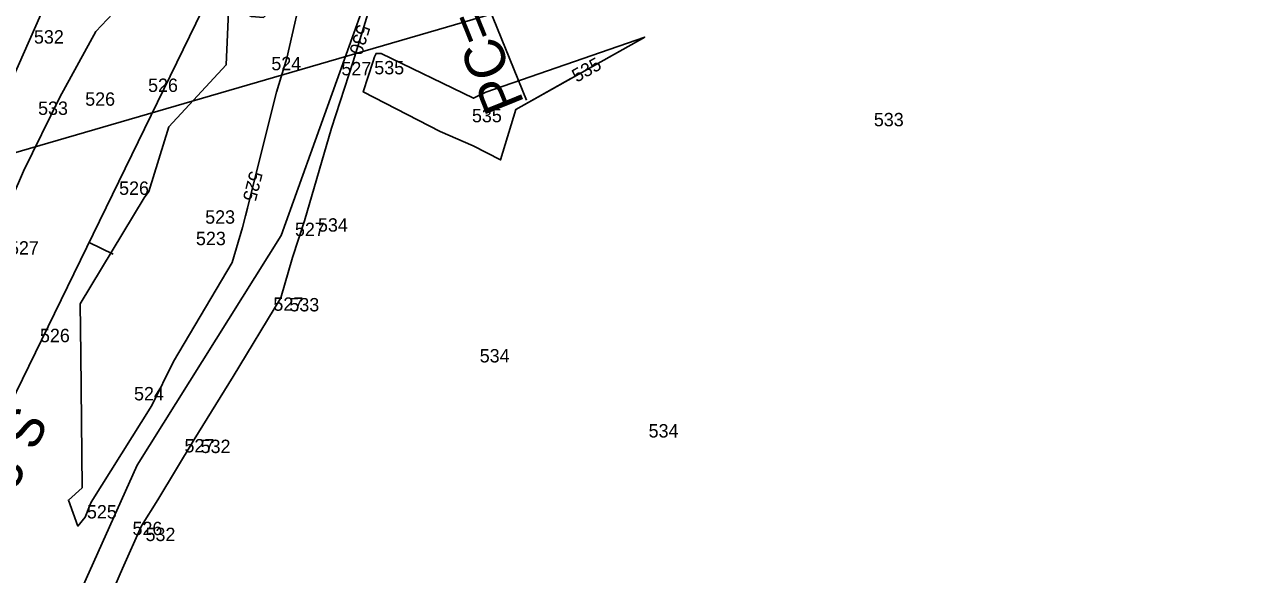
# Model space of a CAD drawing. Extents: x 1787461 to 1970323, y 938412 to 1118748.
# Drawn here: x 1967816.7 to 1967999.8, y 1117714.7 to 1117796.9 of the extents above; entities that cross this region are included whole.
import ezdxf

# ---------------------------------------------------------------- set-up
doc = ezdxf.new("R2010")
doc.units = 0
for name, color, linetype in [('Default', 7, 'Continuous'), ('HHA ADDITIONAL XSs', 7, 'Continuous'), ('Level 1', 7, 'Continuous'), ('RD_EX_DV_Prop', 7, 'Continuous'), ('RD_EX_H2O', 7, 'Continuous'), ('RD_HC_CL', 7, 'Continuous'), ('RD_HC_Data', 7, 'Continuous'), ('RD_HC_Data_Tic', 7, 'Continuous')]:
    doc.layers.add(name, color=color, linetype=linetype)

msp = doc.modelspace()

# ---------------------------------------------------------------- linework, layer by layer
at = {"layer": 'Default'}
for points in [[(1967801.88, 1117847.61), (1967810.59, 1117836.47), (1967817.97, 1117828.1), (1967825.91, 1117816.75), (1967828.59, 1117812.93), (1967832.36, 1117808.61), (1967834.19, 1117807.04), (1967834.93, 1117806.3), (1967834.88, 1117806.26), (1967831.61, 1117800.38), (1967827.33, 1117795.88), (1967821.98, 1117786.05), (1967816.55, 1117775), (1967811.53, 1117763.56), (1967808.3, 1117757.03), (1967806.64, 1117753.26), (1967802.17, 1117742.25), (1967796.95, 1117730.25), (1967792.24, 1117718.65), (1967787.4, 1117707.51)], [(1967801.88, 1117847.61), (1967810.59, 1117836.47), (1967817.97, 1117828.1), (1967825.91, 1117816.75), (1967828.59, 1117812.93), (1967832.36, 1117808.61), (1967834.19, 1117807.04), (1967834.93, 1117806.3), (1967834.88, 1117806.26), (1967831.61, 1117800.38), (1967827.33, 1117795.88), (1967821.98, 1117786.05), (1967816.55, 1117775), (1967811.53, 1117763.56), (1967808.3, 1117757.03), (1967806.64, 1117753.26), (1967802.17, 1117742.25), (1967796.95, 1117730.25), (1967792.24, 1117718.65), (1967787.4, 1117707.51)], [(1967801.88, 1117847.61), (1967810.59, 1117836.47), (1967817.97, 1117828.1), (1967825.91, 1117816.75), (1967828.59, 1117812.93), (1967832.36, 1117808.61), (1967834.19, 1117807.04), (1967834.93, 1117806.3), (1967834.88, 1117806.26), (1967831.61, 1117800.38), (1967827.33, 1117795.88), (1967821.98, 1117786.05), (1967816.55, 1117775), (1967811.53, 1117763.56), (1967808.3, 1117757.03), (1967806.64, 1117753.26), (1967802.17, 1117742.25), (1967796.95, 1117730.25), (1967792.24, 1117718.65), (1967787.4, 1117707.51)], [(1967801.88, 1117847.61), (1967810.59, 1117836.47), (1967817.97, 1117828.1), (1967825.91, 1117816.75), (1967828.59, 1117812.93), (1967832.36, 1117808.61), (1967834.19, 1117807.04), (1967834.93, 1117806.3), (1967834.88, 1117806.26), (1967831.61, 1117800.38), (1967827.33, 1117795.88), (1967821.98, 1117786.05), (1967816.55, 1117775), (1967811.53, 1117763.56), (1967808.3, 1117757.03), (1967806.64, 1117753.26), (1967802.17, 1117742.25), (1967796.95, 1117730.25), (1967792.24, 1117718.65), (1967787.4, 1117707.51)], [(1967801.88, 1117847.61), (1967810.59, 1117836.47), (1967817.97, 1117828.1), (1967825.91, 1117816.75), (1967828.59, 1117812.93), (1967832.36, 1117808.61), (1967834.19, 1117807.04), (1967834.93, 1117806.3), (1967834.88, 1117806.26), (1967831.61, 1117800.38), (1967827.33, 1117795.88), (1967821.98, 1117786.05), (1967816.55, 1117775), (1967811.53, 1117763.56), (1967808.3, 1117757.03), (1967806.64, 1117753.26), (1967802.17, 1117742.25), (1967796.95, 1117730.25), (1967792.24, 1117718.65), (1967787.4, 1117707.51)], [(1967801.88, 1117847.61), (1967810.59, 1117836.47), (1967817.97, 1117828.1), (1967825.91, 1117816.75), (1967828.59, 1117812.93), (1967832.36, 1117808.61), (1967834.19, 1117807.04), (1967834.93, 1117806.3), (1967834.88, 1117806.26), (1967831.61, 1117800.38), (1967827.33, 1117795.88), (1967821.98, 1117786.05), (1967816.55, 1117775), (1967811.53, 1117763.56), (1967808.3, 1117757.03), (1967806.64, 1117753.26), (1967802.17, 1117742.25), (1967796.95, 1117730.25), (1967792.24, 1117718.65), (1967787.4, 1117707.51)], [(1967810.59, 1117836.47), (1967817.97, 1117828.1), (1967825.91, 1117816.75), (1967828.59, 1117812.93), (1967832.36, 1117808.61), (1967834.19, 1117807.04), (1967834.93, 1117806.3), (1967834.88, 1117806.26), (1967831.61, 1117800.38), (1967827.33, 1117795.88), (1967821.98, 1117786.05), (1967816.55, 1117775)], [(1967825.01, 1117755.18), (1967834.57, 1117771.02), (1967835.27, 1117771.98), (1967838.28, 1117781.65), (1967846.84, 1117790.9), (1967847.21, 1117799.97), (1967850.61, 1117798.14), (1967852.43, 1117798), (1967858.52, 1117803.53), (1967855.88, 1117791.92), (1967854.34, 1117786.82), (1967849.71, 1117768.33), (1967849.28, 1117766.59), (1967847.71, 1117761.38), (1967838.96, 1117746.55), (1967835.72, 1117740.01), (1967826.65, 1117725.53), (1967826.39, 1117724.96), (1967825.77, 1117723.3), (1967824.68, 1117721.97), (1967823.26, 1117725.85), (1967825.32, 1117727.69), (1967825.09, 1117747.68), (1967825.01, 1117755.18)], [(1967824.16, 1117699.1), (1967831.36, 1117715.62), (1967834.2, 1117721.99), (1967836.61, 1117725.9), (1967842.06, 1117734.92), (1967847.86, 1117744.33), (1967854.99, 1117756.1), (1967856.74, 1117762.12), (1967858.55, 1117767.59), (1967862.58, 1117781.44), (1967865.81, 1117791.38), (1967869.95, 1117804.92)], [(1967825.01, 1117755.18), (1967834.57, 1117771.02), (1967835.27, 1117771.98), (1967838.28, 1117781.65), (1967846.84, 1117790.9), (1967847.21, 1117799.97), (1967850.61, 1117798.14), (1967852.43, 1117798), (1967858.52, 1117803.53), (1967855.88, 1117791.92), (1967854.34, 1117786.82), (1967851.45, 1117775.29)], [(1967825.01, 1117755.18), (1967834.57, 1117771.02), (1967835.27, 1117771.98), (1967838.28, 1117781.65), (1967846.84, 1117790.9), (1967847.21, 1117799.97), (1967850.61, 1117798.14), (1967852.43, 1117798), (1967858.52, 1117803.53), (1967855.88, 1117791.92), (1967854.34, 1117786.82), (1967851.45, 1117775.29)], [(1967825.01, 1117755.18), (1967834.57, 1117771.02), (1967835.27, 1117771.98), (1967838.28, 1117781.65), (1967846.84, 1117790.9), (1967847.21, 1117799.97), (1967850.61, 1117798.14), (1967852.43, 1117798), (1967858.52, 1117803.53), (1967855.88, 1117791.92), (1967854.34, 1117786.82), (1967851.45, 1117775.29)], [(1967825.01, 1117755.18), (1967834.57, 1117771.02), (1967835.27, 1117771.98), (1967838.28, 1117781.65), (1967846.84, 1117790.9), (1967847.21, 1117799.97), (1967850.61, 1117798.14), (1967852.43, 1117798), (1967858.52, 1117803.53), (1967855.88, 1117791.92), (1967854.34, 1117786.82), (1967851.45, 1117775.29)], [(1967825.01, 1117755.18), (1967834.57, 1117771.02), (1967835.27, 1117771.98), (1967838.28, 1117781.65), (1967846.84, 1117790.9), (1967847.21, 1117799.97), (1967850.61, 1117798.14), (1967852.43, 1117798), (1967858.52, 1117803.53), (1967855.88, 1117791.92), (1967854.34, 1117786.82), (1967851.45, 1117775.29)], [(1967825.01, 1117755.18), (1967834.57, 1117771.02), (1967835.27, 1117771.98), (1967838.28, 1117781.65), (1967846.84, 1117790.9), (1967847.21, 1117799.97), (1967850.61, 1117798.14), (1967852.43, 1117798), (1967858.52, 1117803.53), (1967855.88, 1117791.92), (1967854.34, 1117786.82), (1967851.45, 1117775.29)], [(1967868.82, 1117791.47), (1967869.02, 1117792.12), (1967869.25, 1117792.62), (1967870.02, 1117792.58), (1967883.8, 1117785.91), (1967885.65, 1117786.84), (1967909.41, 1117795.06), (1967890.14, 1117784.25), (1967887.87, 1117776.68), (1967883.76, 1117778.78), (1967878.84, 1117780.96), (1967867.32, 1117786.85), (1967868.82, 1117791.47)], [(1967868.82, 1117791.47), (1967869.02, 1117792.12), (1967869.25, 1117792.62), (1967870.02, 1117792.58), (1967883.8, 1117785.91), (1967885.65, 1117786.84), (1967909.41, 1117795.06), (1967903.62, 1117791.81)], [(1967868.82, 1117791.47), (1967869.02, 1117792.12), (1967869.25, 1117792.62), (1967870.02, 1117792.58), (1967883.8, 1117785.91), (1967885.65, 1117786.84), (1967909.41, 1117795.06), (1967903.62, 1117791.81)], [(1967868.82, 1117791.47), (1967869.02, 1117792.12), (1967869.25, 1117792.62), (1967870.02, 1117792.58), (1967883.8, 1117785.91), (1967885.65, 1117786.84), (1967909.41, 1117795.06), (1967903.62, 1117791.81)], [(1967868.82, 1117791.47), (1967869.02, 1117792.12), (1967869.25, 1117792.62), (1967870.02, 1117792.58), (1967883.8, 1117785.91), (1967885.65, 1117786.84), (1967909.41, 1117795.06), (1967903.62, 1117791.81)], [(1967868.82, 1117791.47), (1967869.02, 1117792.12), (1967869.25, 1117792.62), (1967870.02, 1117792.58), (1967883.8, 1117785.91), (1967885.65, 1117786.84), (1967909.41, 1117795.06), (1967903.62, 1117791.81)], [(1967868.82, 1117791.47), (1967869.02, 1117792.12), (1967869.25, 1117792.62), (1967870.02, 1117792.58), (1967883.8, 1117785.91), (1967885.65, 1117786.84), (1967909.41, 1117795.06), (1967903.62, 1117791.81)], [(1967785.77, 1117609.46), (1967789.86, 1117617.86), (1967798.49, 1117629.43), (1967798.85, 1117630.5), (1967799.16, 1117631.38), (1967803.98, 1117645.6), (1967807.24, 1117654.97), (1967814.41, 1117676.3), (1967815.2, 1117678.59), (1967815.94, 1117680.25), (1967824.16, 1117699.1), (1967831.36, 1117715.62), (1967834.2, 1117721.99), (1967836.61, 1117725.9), (1967842.06, 1117734.92), (1967847.86, 1117744.33), (1967854.99, 1117756.1), (1967856.74, 1117762.12), (1967858.55, 1117767.59), (1967862.58, 1117781.44), (1967865.81, 1117791.38), (1967865.83, 1117791.44)], [(1967785.77, 1117609.46), (1967789.86, 1117617.86), (1967798.49, 1117629.43), (1967798.85, 1117630.5), (1967799.16, 1117631.38), (1967803.98, 1117645.6), (1967807.24, 1117654.97), (1967814.41, 1117676.3), (1967815.2, 1117678.59), (1967815.94, 1117680.25), (1967824.16, 1117699.1), (1967831.36, 1117715.62), (1967834.2, 1117721.99), (1967836.61, 1117725.9), (1967842.06, 1117734.92), (1967847.86, 1117744.33), (1967854.99, 1117756.1), (1967856.74, 1117762.12), (1967858.55, 1117767.59), (1967862.58, 1117781.44), (1967865.81, 1117791.38), (1967865.83, 1117791.44)], [(1967785.77, 1117609.46), (1967789.86, 1117617.86), (1967798.49, 1117629.43), (1967798.85, 1117630.5), (1967799.16, 1117631.38), (1967803.98, 1117645.6), (1967807.24, 1117654.97), (1967814.41, 1117676.3), (1967815.2, 1117678.59), (1967815.94, 1117680.25), (1967824.16, 1117699.1), (1967831.36, 1117715.62), (1967834.2, 1117721.99), (1967836.61, 1117725.9), (1967842.06, 1117734.92), (1967847.86, 1117744.33), (1967854.99, 1117756.1), (1967856.74, 1117762.12), (1967858.55, 1117767.59), (1967862.58, 1117781.44), (1967865.81, 1117791.38), (1967865.83, 1117791.44)], [(1967785.77, 1117609.46), (1967789.86, 1117617.86), (1967798.49, 1117629.43), (1967798.85, 1117630.5), (1967799.16, 1117631.38), (1967803.98, 1117645.6), (1967807.24, 1117654.97), (1967814.41, 1117676.3), (1967815.2, 1117678.59), (1967815.94, 1117680.25), (1967824.16, 1117699.1), (1967831.36, 1117715.62), (1967834.2, 1117721.99), (1967836.61, 1117725.9), (1967842.06, 1117734.92), (1967847.86, 1117744.33), (1967854.99, 1117756.1), (1967856.74, 1117762.12), (1967858.55, 1117767.59), (1967862.58, 1117781.44), (1967865.81, 1117791.38), (1967865.83, 1117791.44)], [(1967785.77, 1117609.46), (1967789.86, 1117617.86), (1967798.49, 1117629.43), (1967798.85, 1117630.5), (1967799.16, 1117631.38), (1967803.98, 1117645.6), (1967807.24, 1117654.97), (1967814.41, 1117676.3), (1967815.2, 1117678.59), (1967815.94, 1117680.25), (1967824.16, 1117699.1), (1967831.36, 1117715.62), (1967834.2, 1117721.99), (1967836.61, 1117725.9), (1967842.06, 1117734.92), (1967847.86, 1117744.33), (1967854.99, 1117756.1), (1967856.74, 1117762.12), (1967858.55, 1117767.59), (1967862.58, 1117781.44), (1967865.81, 1117791.38), (1967865.83, 1117791.44)], [(1967785.77, 1117609.46), (1967789.86, 1117617.86), (1967798.49, 1117629.43), (1967798.85, 1117630.5), (1967799.16, 1117631.38), (1967803.98, 1117645.6), (1967807.24, 1117654.97), (1967814.41, 1117676.3), (1967815.2, 1117678.59), (1967815.94, 1117680.25), (1967824.16, 1117699.1), (1967831.36, 1117715.62), (1967834.2, 1117721.99), (1967836.61, 1117725.9), (1967842.06, 1117734.92), (1967847.86, 1117744.33), (1967854.99, 1117756.1), (1967856.74, 1117762.12), (1967858.55, 1117767.59), (1967862.58, 1117781.44), (1967865.81, 1117791.38), (1967865.83, 1117791.44)], [(1967898.38, 1117788.88), (1967890.14, 1117784.25), (1967887.87, 1117776.68), (1967883.76, 1117778.78), (1967878.84, 1117780.96), (1967867.32, 1117786.85), (1967868.82, 1117791.47)], [(1967898.38, 1117788.88), (1967890.14, 1117784.25), (1967887.87, 1117776.68), (1967883.76, 1117778.78), (1967878.84, 1117780.96), (1967867.32, 1117786.85), (1967868.82, 1117791.47)], [(1967898.38, 1117788.88), (1967890.14, 1117784.25), (1967887.87, 1117776.68), (1967883.76, 1117778.78), (1967878.84, 1117780.96), (1967867.32, 1117786.85), (1967868.82, 1117791.47)], [(1967898.38, 1117788.88), (1967890.14, 1117784.25), (1967887.87, 1117776.68), (1967883.76, 1117778.78), (1967878.84, 1117780.96), (1967867.32, 1117786.85), (1967868.82, 1117791.47)], [(1967898.38, 1117788.88), (1967890.14, 1117784.25), (1967887.87, 1117776.68), (1967883.76, 1117778.78), (1967878.84, 1117780.96), (1967867.32, 1117786.85), (1967868.82, 1117791.47)], [(1967898.38, 1117788.88), (1967890.14, 1117784.25), (1967887.87, 1117776.68), (1967883.76, 1117778.78), (1967878.84, 1117780.96), (1967867.32, 1117786.85), (1967868.82, 1117791.47)], [(1967850, 1117769.47), (1967849.71, 1117768.33), (1967849.28, 1117766.59), (1967847.71, 1117761.38), (1967838.96, 1117746.55), (1967835.72, 1117740.01), (1967826.65, 1117725.53), (1967826.39, 1117724.96), (1967825.77, 1117723.3), (1967824.68, 1117721.97), (1967823.26, 1117725.85), (1967825.32, 1117727.69), (1967825.09, 1117747.68), (1967825.01, 1117755.18)], [(1967850, 1117769.47), (1967849.71, 1117768.33), (1967849.28, 1117766.59), (1967847.71, 1117761.38), (1967838.96, 1117746.55), (1967835.72, 1117740.01), (1967826.65, 1117725.53), (1967826.39, 1117724.96), (1967825.77, 1117723.3), (1967824.68, 1117721.97), (1967823.26, 1117725.85), (1967825.32, 1117727.69), (1967825.09, 1117747.68), (1967825.01, 1117755.18)], [(1967850, 1117769.47), (1967849.71, 1117768.33), (1967849.28, 1117766.59), (1967847.71, 1117761.38), (1967838.96, 1117746.55), (1967835.72, 1117740.01), (1967826.65, 1117725.53), (1967826.39, 1117724.96), (1967825.77, 1117723.3), (1967824.68, 1117721.97), (1967823.26, 1117725.85), (1967825.32, 1117727.69), (1967825.09, 1117747.68), (1967825.01, 1117755.18)], [(1967850, 1117769.47), (1967849.71, 1117768.33), (1967849.28, 1117766.59), (1967847.71, 1117761.38), (1967838.96, 1117746.55), (1967835.72, 1117740.01), (1967826.65, 1117725.53), (1967826.39, 1117724.96), (1967825.77, 1117723.3), (1967824.68, 1117721.97), (1967823.26, 1117725.85), (1967825.32, 1117727.69), (1967825.09, 1117747.68), (1967825.01, 1117755.18)], [(1967850, 1117769.47), (1967849.71, 1117768.33), (1967849.28, 1117766.59), (1967847.71, 1117761.38), (1967838.96, 1117746.55), (1967835.72, 1117740.01), (1967826.65, 1117725.53), (1967826.39, 1117724.96), (1967825.77, 1117723.3), (1967824.68, 1117721.97), (1967823.26, 1117725.85), (1967825.32, 1117727.69), (1967825.09, 1117747.68), (1967825.01, 1117755.18)], [(1967850, 1117769.47), (1967849.71, 1117768.33), (1967849.28, 1117766.59), (1967847.71, 1117761.38), (1967838.96, 1117746.55), (1967835.72, 1117740.01), (1967826.65, 1117725.53), (1967826.39, 1117724.96), (1967825.77, 1117723.3), (1967824.68, 1117721.97), (1967823.26, 1117725.85), (1967825.32, 1117727.69), (1967825.09, 1117747.68), (1967825.01, 1117755.18)]]:
    msp.add_lwpolyline(points, dxfattribs=at)
at = {"layer": 'HHA ADDITIONAL XSs'}
msp.add_arc((1968231.34, 1116297.54), 1607.02, 87.72663, 111.99584, dxfattribs=at)
at = {"layer": 'Level 1'}
msp.add_lwpolyline([(1968654.57, 1117840.68), (1968058.24, 1117848.48), (1967686.38, 1117740.3), (1966964.76, 1117453.35)], dxfattribs=at)
at = {"layer": 'RD_EX_DV_Prop'}
msp.add_line((1967848.59, 1117809.96), (1967728.08, 1117563.01), dxfattribs=at)
at = {"layer": 'RD_EX_H2O'}
for points in [[(1967793.07, 1117884.81), (1967795.4, 1117862.79), (1967808.44, 1117844.76), (1967827.6, 1117817.64), (1967803.85, 1117763.92), (1967785.1, 1117717.4), (1967778.96, 1117698.7), (1967761.45, 1117660.55), (1967735.16, 1117625.66), (1967726.1, 1117620.57), (1967713.81, 1117582.71), (1967729.78, 1117524.09), (1967774.63, 1117477.47), (1967792.06, 1117468.24), (1967815.16, 1117463.54)], [(1967872.32, 1117822.66), (1967872.31, 1117820.09), (1967867.75, 1117800.84), (1967855.06, 1117765.41), (1967833.55, 1117731.08), (1967814.13, 1117687.88), (1967798.73, 1117637.75), (1967777.02, 1117596.99), (1967770.1, 1117591.47), (1967755.23, 1117573.96), (1967763.13, 1117553.21), (1967794.74, 1117526.69), (1967804.69, 1117522.56), (1967827.72, 1117512.92)]]:
    msp.add_lwpolyline(points, dxfattribs=at)
at = {"layer": 'RD_HC_CL'}
msp.add_line((1967848.59, 1117809.96), (1967728.08, 1117563.01), dxfattribs=at)
at = {"layer": 'RD_HC_Data'}
msp.add_line((1967848.24, 1117893.22), (1967891.71, 1117785.61), dxfattribs=at)
at = {"layer": 'RD_HC_Data_Tic'}
msp.add_line((1967826.33, 1117764.34), (1967829.92, 1117762.59), dxfattribs=at)

# ---------------------------------------------------------------- texts
at = {"layer": 'Default'}
for s, rotation, p in [('530', 252.9925, (1967866.51, 1117797.07)), ('530', 252.9925, (1967866.51, 1117797.07)), ('530', 252.9925, (1967866.51, 1117797.07)), ('530', 252.9925, (1967866.51, 1117797.07)), ('530', 252.9925, (1967866.51, 1117797.07)), ('530', 252.9925, (1967866.51, 1117797.07)), ('535', 29.2663, (1967899.24, 1117788.21)), ('535', 29.2663, (1967899.24, 1117788.21)), ('535', 29.2663, (1967899.24, 1117788.21)), ('535', 29.2663, (1967899.24, 1117788.21)), ('535', 29.2663, (1967899.24, 1117788.21)), ('535', 29.2663, (1967899.24, 1117788.21)), ('525', 255.9581, (1967850.39, 1117775.16)), ('525', 255.9581, (1967850.39, 1117775.16)), ('525', 255.9581, (1967850.39, 1117775.16)), ('525', 255.9581, (1967850.39, 1117775.16)), ('525', 255.9581, (1967850.39, 1117775.16)), ('525', 255.9581, (1967850.39, 1117775.16))]:
    msp.add_text(s, height=2, rotation=rotation, dxfattribs=at).set_placement(p)
for s, p in [('532', (1967818.1, 1117794.08)), ('524', (1967853.59, 1117790.09)), ('527', (1967864.06, 1117789.33)), ('535', (1967868.98, 1117789.48)), ('526', (1967835.16, 1117786.85)), ('533', (1967818.72, 1117783.42)), ('526', (1967825.76, 1117784.79)), ('535', (1967883.58, 1117782.32)), ('533', (1967943.66, 1117781.72)), ('526', (1967830.83, 1117771.47)), ('523', (1967843.7, 1117767.16)), ('527', (1967857.12, 1117765.31)), ('534', (1967860.56, 1117765.97)), ('523', (1967842.32, 1117763.95)), ('527', (1967814.37, 1117762.54)), ('527', (1967853.89, 1117754.14)), ('533', (1967856.29, 1117754.05)), ('526', (1967819, 1117749.45)), ('534', (1967884.74, 1117746.42)), ('524', (1967833.06, 1117740.75)), ('534', (1967909.99, 1117735.2)), ('527', (1967840.6, 1117732.97)), ('532', (1967843.02, 1117732.88)), ('525', (1967826.02, 1117723.1)), ('526', (1967832.83, 1117720.61)), ('532', (1967834.78, 1117719.72))]:
    msp.add_text(s, height=2, dxfattribs=at).set_placement(p)
at = {"layer": 'RD_HC_Data'}
for s, rotation, p in [('PC=61+63.41', 111.9958, (1967891.47, 1117785.18)), ('S 26%%d 00\' 44" W', 243.9877, (1967815.06, 1117740.34))]:
    msp.add_text(s, height=6, rotation=rotation, dxfattribs=at).set_placement(p)

doc.saveas('drawing.dxf')
